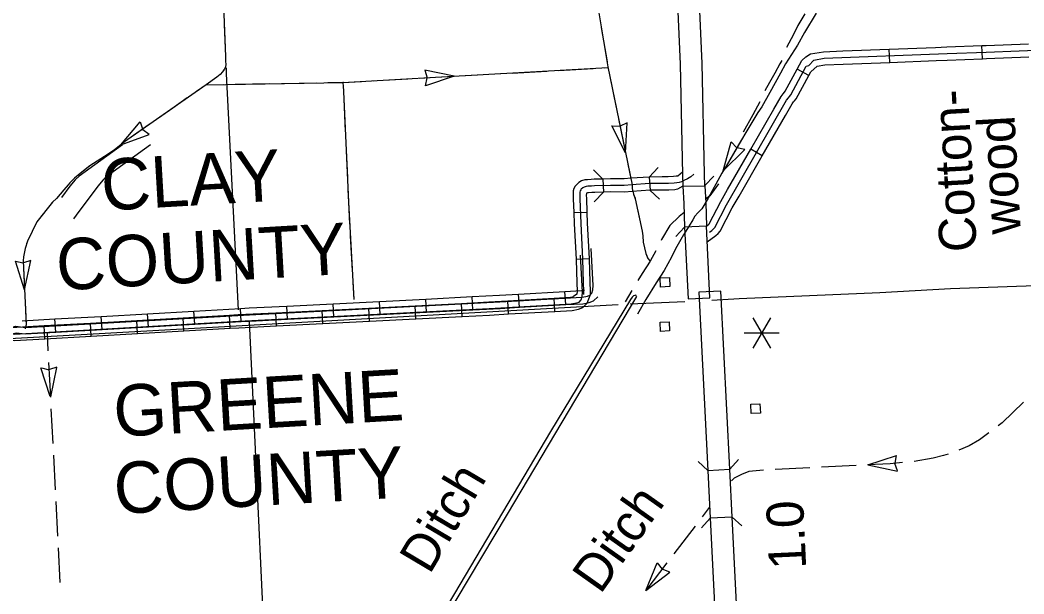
# Model space of a CAD drawing. Extents: x -0.3 to 2.65, y 0 to 1.9.
# Drawn here: x 0.7254 to 0.8619, y 0.3171 to 0.3953 of the extents above; entities that cross this region are included whole.
import ezdxf

# ---------------------------------------------------------------- set-up
doc = ezdxf.new("R2010")
doc.units = 0
for name, color, linetype in [('Level 10', 7, 'Continuous'), ('Level 12', 7, 'Continuous'), ('Level 13', 7, 'Continuous'), ('Level 14', 7, 'Continuous'), ('Level 15', 7, 'Continuous'), ('Level 16', 7, 'Continuous'), ('Level 19', 7, 'Continuous'), ('Level 20', 7, 'Continuous'), ('Level 21', 7, 'Continuous'), ('Level 23', 7, 'Continuous'), ('Level 29', 7, 'Continuous'), ('Level 30', 7, 'Continuous')]:
    doc.layers.add(name, color=color, linetype=linetype)

msp = doc.modelspace()

# ---------------------------------------------------------------- linework, layer by layer
at = {"layer": 'Level 12'}
for p, q in [((0.78041, 0.38846), (0.78075, 0.38742)), ((0.78443, 0.38762), (0.78041, 0.38846)), ((0.78443, 0.38762), (0.78053, 0.38634)), ((0.78053, 0.38634), (0.78075, 0.38741)), ((0.73907, 0.37828), (0.7417, 0.38143)), ((0.7417, 0.38143), (0.74204, 0.38035)), ((0.80797, 0.3813), (0.80699, 0.38081)), ((0.80772, 0.3772), (0.80797, 0.3813)), ((0.74292, 0.37969), (0.74204, 0.38035)), ((0.80772, 0.3772), (0.80589, 0.38088)), ((0.80589, 0.38088), (0.80698, 0.38081)), ((0.73907, 0.37828), (0.74292, 0.37969)), ((0.82103, 0.37475), (0.82213, 0.37871)), ((0.82213, 0.37871), (0.8229, 0.37789)), ((0.82103, 0.37475), (0.82396, 0.37763)), ((0.82396, 0.37763), (0.8229, 0.37789)), ((0.72684, 0.36254), (0.7258, 0.36221)), ((0.72597, 0.35853), (0.72684, 0.36254)), ((0.72945, 0.34402), (0.72819, 0.34793)), ((0.72826, 0.34791), (0.72932, 0.34766)), ((0.73038, 0.34801), (0.72934, 0.34769)), ((0.72952, 0.34396), (0.73038, 0.34797)), ((0.84071, 0.3347), (0.84462, 0.33596)), ((0.84071, 0.3347), (0.84473, 0.33384)), ((0.84458, 0.33599), (0.84439, 0.33491)), ((0.84476, 0.33387), (0.84439, 0.3349)), ((0.8105, 0.31757), (0.81206, 0.32137)), ((0.81206, 0.32137), (0.81273, 0.3205)), ((0.8105, 0.31757), (0.81375, 0.32008)), ((0.81375, 0.32008), (0.81274, 0.32049))]:
    msp.add_line(p, q, dxfattribs=at)
for points in [[(0.79106, 0.46314), (0.79518, 0.44993), (0.79538, 0.44924), (0.79554, 0.44865), (0.79566, 0.44801), (0.79581, 0.4473), (0.80033, 0.41993), (0.80169, 0.41097), (0.80222, 0.40776), (0.80533, 0.3889), (0.80862, 0.37283), (0.80865, 0.37236), (0.80883, 0.37157), (0.80906, 0.37094), (0.80998, 0.36655), (0.81009, 0.36589), (0.81015, 0.36502), (0.81051, 0.36349), (0.81075, 0.3628), (0.81108, 0.36244)], [(0.75278, 0.40422), (0.75329, 0.39033), (0.75329, 0.38968), (0.75333, 0.38925), (0.75331, 0.3889), (0.75318, 0.38857), (0.75292, 0.38824), (0.7526, 0.38788), (0.75215, 0.38752), (0.75067, 0.38648), (0.73956, 0.37868), (0.73818, 0.37755), (0.73684, 0.37672), (0.73487, 0.37543), (0.73352, 0.37437), (0.73276, 0.37373), (0.73214, 0.3731), (0.7319, 0.37284), (0.73131, 0.37218), (0.73029, 0.37098), (0.72977, 0.37046), (0.72762, 0.36781)], [(0.83366, 0.39622), (0.83211, 0.39357), (0.83114, 0.39187), (0.82952, 0.3893), (0.82884, 0.38803), (0.82808, 0.38674), (0.82737, 0.38542), (0.82629, 0.38348), (0.82575, 0.3827), (0.8241, 0.37998), (0.82351, 0.37899), (0.82143, 0.37537), (0.82082, 0.37443), (0.81896, 0.37103), (0.81811, 0.36959), (0.81757, 0.36902), (0.81718, 0.36858), (0.81689, 0.36808), (0.81639, 0.36724), (0.81564, 0.36604), (0.81453, 0.36411), (0.81398, 0.36301), (0.81298, 0.36117), (0.8119, 0.35949), (0.81051, 0.35721), (0.80937, 0.35523)], [(0.83212, 0.39612), (0.83119, 0.39453), (0.8306, 0.39333), (0.82965, 0.39156)], [(0.75313, 0.39474), (0.75329, 0.39033), (0.75329, 0.39)], [(0.80444, 0.39426), (0.80522, 0.38959)], [(0.82902, 0.38977), (0.82875, 0.38933), (0.82807, 0.38806), (0.82731, 0.38677), (0.8267, 0.38564)], [(0.7531, 0.38848), (0.75292, 0.38824), (0.7526, 0.38788), (0.75215, 0.38752), (0.75067, 0.38648), (0.74938, 0.38557)], [(0.75067, 0.38648), (0.76937, 0.38679), (0.76929, 0.38677), (0.77393, 0.38704), (0.78187, 0.38748), (0.80531, 0.38881)], [(0.78837, 0.38785), (0.79074, 0.38798)], [(0.79231, 0.38807), (0.79705, 0.38834)], [(0.79862, 0.38843), (0.80335, 0.3887)], [(0.80493, 0.38879), (0.80531, 0.38881)], [(0.80551, 0.38804), (0.80646, 0.38339)], [(0.75462, 0.38655), (0.75936, 0.38663)], [(0.76094, 0.38665), (0.76568, 0.38673)], [(0.76725, 0.38676), (0.76937, 0.38679), (0.76929, 0.38677), (0.77181, 0.38692)], [(0.7708, 0.35723), (0.77007, 0.37048), (0.76945, 0.38455), (0.76938, 0.38643), (0.76929, 0.38677)], [(0.76938, 0.38642), (0.76938, 0.38643), (0.76929, 0.38677)], [(0.77339, 0.38701), (0.77393, 0.38704), (0.77812, 0.38727)], [(0.7797, 0.38736), (0.78187, 0.38748), (0.78443, 0.38762)], [(0.78601, 0.38771), (0.78837, 0.38785)], [(0.75067, 0.38648), (0.75304, 0.38652)], [(0.74809, 0.38467), (0.74615, 0.3833)], [(0.76965, 0.3801), (0.76945, 0.38455), (0.76944, 0.38484)], [(0.82602, 0.38415), (0.82507, 0.38237), (0.82376, 0.37999)], [(0.74615, 0.3833), (0.74421, 0.38194)], [(0.80677, 0.38185), (0.80772, 0.3772)], [(0.74292, 0.38104), (0.73956, 0.37868), (0.73907, 0.37828)], [(0.76993, 0.37379), (0.76972, 0.37853)], [(0.82343, 0.37884), (0.82143, 0.37537), (0.82103, 0.37475)], [(0.73781, 0.37732), (0.73684, 0.37672), (0.73487, 0.37543), (0.73389, 0.37466)], [(0.80804, 0.37566), (0.80844, 0.37372)], [(0.73268, 0.37365), (0.73214, 0.3731), (0.7319, 0.37284), (0.73131, 0.37218), (0.73029, 0.37098), (0.72977, 0.37046), (0.72951, 0.37014)], [(0.82038, 0.37299), (0.8192, 0.37133), (0.81863, 0.3709)], [(0.77024, 0.36748), (0.77007, 0.37048), (0.77, 0.37222)], [(0.80875, 0.37194), (0.80883, 0.37157), (0.80903, 0.37103)], [(0.72851, 0.36891), (0.72762, 0.36781), (0.72762, 0.36781), (0.72636, 0.36515), (0.72625, 0.36479)], [(0.80937, 0.36949), (0.80998, 0.36655), (0.81009, 0.36589), (0.81015, 0.36502), (0.8102, 0.36483)], [(0.81571, 0.36907), (0.81503, 0.36854), (0.81375, 0.36732), (0.81375, 0.36732)], [(0.72762, 0.36781), (0.72636, 0.36515), (0.72606, 0.36415), (0.7258, 0.36305), (0.72578, 0.36249), (0.72619, 0.3539), (0.72615, 0.35365), (0.72604, 0.35323)], [(0.81375, 0.36732), (0.81264, 0.36539), (0.81257, 0.36526)], [(0.77058, 0.36117), (0.77033, 0.36591)], [(0.81185, 0.36386), (0.81108, 0.36244), (0.81, 0.36076), (0.80941, 0.3598)], [(0.72585, 0.36326), (0.7258, 0.36305), (0.72578, 0.36249), (0.72597, 0.35853)], [(0.81058, 0.3633), (0.81075, 0.3628), (0.81108, 0.36244)], [(0.7708, 0.35723), (0.77067, 0.3596)], [(0.80859, 0.35845), (0.80769, 0.35691)], [(0.72604, 0.35695), (0.72615, 0.35459)], [(0.72615, 0.35459), (0.72619, 0.35371)], [(0.72615, 0.35459), (0.72619, 0.35371)], [(0.72902, 0.3527), (0.72915, 0.35022)], [(0.72923, 0.34864), (0.72935, 0.34628)], [(0.72935, 0.34628), (0.72948, 0.34391)], [(0.86191, 0.34326), (0.859, 0.34043), (0.85846, 0.34003)], [(0.72956, 0.34233), (0.7298, 0.3376)], [(0.85719, 0.33908), (0.8559, 0.33813), (0.8545, 0.33731), (0.85311, 0.33672)], [(0.72989, 0.33602), (0.73013, 0.33129)], [(0.85163, 0.33618), (0.85098, 0.33596), (0.84958, 0.3356), (0.84701, 0.33516)], [(0.84544, 0.335), (0.84376, 0.33485), (0.84071, 0.3347)], [(0.82651, 0.33397), (0.82599, 0.33395), (0.82452, 0.33381), (0.8235, 0.33341), (0.8225, 0.33287), (0.82214, 0.33252)], [(0.83282, 0.33429), (0.82809, 0.33405)], [(0.83913, 0.33462), (0.8344, 0.33437)], [(0.73021, 0.32971), (0.73046, 0.32498)], [(0.81914, 0.32891), (0.81816, 0.32762)], [(0.8172, 0.32636), (0.81433, 0.32259)], [(0.73054, 0.3234), (0.73078, 0.31867)], [(0.81337, 0.32134), (0.8105, 0.31757)]]:
    msp.add_lwpolyline(points, dxfattribs=at)
at = {"layer": 'Level 13'}
for p, q in [((0.84368, 0.38952), (0.84361, 0.39132)), ((0.85631, 0.39001), (0.85624, 0.39181)), ((0.83267, 0.38774), (0.83109, 0.38859)), ((0.82634, 0.37679), (0.82478, 0.37768))]:
    msp.add_line(p, q, dxfattribs=at)
for points in [[(0.85624, 0.39181), (0.8568, 0.39183), (0.86256, 0.39204)], [(0.83109, 0.38859), (0.83173, 0.38977), (0.83225, 0.39029), (0.83291, 0.39068), (0.83467, 0.39096), (0.8373, 0.39107)], [(0.83476, 0.39007), (0.85148, 0.39073), (0.85683, 0.39093), (0.87026, 0.39143), (0.87563, 0.39166), (0.87807, 0.39179)], [(0.8373, 0.39107), (0.84361, 0.39132)], [(0.84361, 0.39132), (0.84993, 0.39156)], [(0.84993, 0.39156), (0.85145, 0.39162), (0.85624, 0.39181)], [(0.81916, 0.36641), (0.81946, 0.36662), (0.8197, 0.36684), (0.81987, 0.36704), (0.82148, 0.37013), (0.82966, 0.38437), (0.82989, 0.38469), (0.83004, 0.38486), (0.83023, 0.38508), (0.83233, 0.389), (0.83266, 0.38908), (0.83336, 0.38984), (0.83476, 0.39007)], [(0.83737, 0.38927), (0.84368, 0.38952)], [(0.84368, 0.38952), (0.85, 0.38977)], [(0.85, 0.38977), (0.85152, 0.38983), (0.85631, 0.39001)], [(0.85631, 0.39001), (0.85687, 0.39003), (0.86262, 0.39025)], [(0.82793, 0.38316), (0.8289, 0.38486), (0.82918, 0.38524), (0.82935, 0.38544), (0.82948, 0.38559), (0.83109, 0.38859)], [(0.83267, 0.38774), (0.83294, 0.38823), (0.83381, 0.38901), (0.83485, 0.38917), (0.83737, 0.38927)], [(0.82949, 0.38227), (0.83041, 0.38388), (0.83059, 0.38413), (0.83072, 0.38428), (0.83097, 0.38457), (0.83267, 0.38774)], [(0.82478, 0.37768), (0.82793, 0.38316)], [(0.82634, 0.37679), (0.82949, 0.38227)], [(0.82163, 0.37221), (0.82478, 0.37768)], [(0.82319, 0.37131), (0.82634, 0.37679)], [(0.81877, 0.3672), (0.81905, 0.36746), (0.81912, 0.36754), (0.82069, 0.37056), (0.82163, 0.37221)], [(0.81884, 0.36509), (0.82003, 0.36592), (0.82035, 0.36621), (0.82062, 0.36653), (0.82226, 0.3697), (0.82319, 0.37131)]]:
    msp.add_lwpolyline(points, dxfattribs=at)
at = {"layer": 'Level 14'}
for points in [[(0.7393, 0.37828), (0.73338, 0.374), (0.73285, 0.37351), (0.73213, 0.37266), (0.73098, 0.37112)], [(0.74312, 0.37828), (0.7372, 0.374), (0.73667, 0.37351), (0.73594, 0.37266), (0.73299, 0.36871), (0.73262, 0.36823)], [(0.80924, 0.35762), (0.80916, 0.35782), (0.8088, 0.35773), (0.80862, 0.35753), (0.8084, 0.35723), (0.79755, 0.33926), (0.77127, 0.2949)], [(0.80924, 0.35762), (0.79164, 0.32797), (0.77248, 0.29587), (0.77149, 0.29411)]]:
    msp.add_lwpolyline(points, dxfattribs=at)
at = {"layer": 'Level 15'}
for p, q in [((0.80467, 0.37363), (0.80472, 0.37184)), ((0.81094, 0.37389), (0.81107, 0.3721)), ((0.80069, 0.36905), (0.80248, 0.36912)), ((0.72597, 0.35853), (0.72472, 0.36244)), ((0.72472, 0.36244), (0.72579, 0.36221)), ((0.801, 0.36273), (0.8028, 0.36282)), ((0.79329, 0.35616), (0.79319, 0.35795)), ((0.7996, 0.35652), (0.7995, 0.35831)), ((0.76805, 0.35486), (0.76795, 0.35665)), ((0.77436, 0.35518), (0.77426, 0.35697)), ((0.78067, 0.3555), (0.78057, 0.35729)), ((0.7855, 0.35491), (0.78541, 0.3567)), ((0.78698, 0.35582), (0.78688, 0.35761)), ((0.79181, 0.35525), (0.79171, 0.35704)), ((0.79812, 0.35561), (0.79802, 0.3574)), ((0.74281, 0.35349), (0.74271, 0.35528)), ((0.74912, 0.35385), (0.74902, 0.35564)), ((0.75543, 0.35421), (0.75533, 0.356)), ((0.76026, 0.35363), (0.76017, 0.35542)), ((0.76174, 0.35454), (0.76164, 0.35633)), ((0.76657, 0.35395), (0.76648, 0.35574)), ((0.77288, 0.35427), (0.77279, 0.35606)), ((0.77919, 0.35459), (0.7791, 0.35638)), ((0.7302, 0.35277), (0.7301, 0.35457)), ((0.73503, 0.35222), (0.73493, 0.35402)), ((0.73651, 0.35313), (0.73641, 0.35492)), ((0.74134, 0.35258), (0.74124, 0.35437)), ((0.74765, 0.35294), (0.74754, 0.35473)), ((0.75395, 0.3533), (0.75385, 0.35509)), ((0.72872, 0.35187), (0.72862, 0.35366))]:
    msp.add_line(p, q, dxfattribs=at)
for points in [[(0.81701, 0.37427), (0.81663, 0.37394), (0.81615, 0.37365), (0.81568, 0.37341), (0.81537, 0.37327), (0.81505, 0.37316), (0.81472, 0.37312), (0.81434, 0.37308), (0.81359, 0.37301), (0.81273, 0.37302), (0.81101, 0.373), (0.80858, 0.37283), (0.80757, 0.37276), (0.80571, 0.37276), (0.8035, 0.3727), (0.80311, 0.37267), (0.80263, 0.37264), (0.80239, 0.37262), (0.80211, 0.37254), (0.80191, 0.37243), (0.80172, 0.37226), (0.80164, 0.37217), (0.80156, 0.37201), (0.80151, 0.37186), (0.8015, 0.37144), (0.80151, 0.37094), (0.80164, 0.36758), (0.8019, 0.36271), (0.80199, 0.35953), (0.80204, 0.35835), (0.80203, 0.35792)], [(0.8155, 0.37458), (0.81485, 0.37404), (0.81461, 0.37401), (0.81426, 0.37397), (0.81356, 0.37391), (0.81273, 0.37392), (0.81097, 0.37389), (0.81094, 0.37389)], [(0.80467, 0.37363), (0.80346, 0.3736), (0.80305, 0.37357), (0.80256, 0.37354), (0.80222, 0.37351), (0.80175, 0.37337), (0.80139, 0.37316), (0.80109, 0.3729), (0.80088, 0.37268), (0.80072, 0.37235), (0.80062, 0.37201), (0.8006, 0.37144), (0.80062, 0.37091), (0.80069, 0.36905)], [(0.81094, 0.37389), (0.80852, 0.37373), (0.80754, 0.37366), (0.8057, 0.37366), (0.80467, 0.37363)], [(0.80472, 0.37184), (0.80354, 0.3718), (0.80317, 0.37178), (0.8027, 0.37175), (0.80255, 0.37173), (0.80246, 0.37171), (0.80242, 0.37169), (0.80241, 0.37167), (0.8024, 0.37144), (0.80241, 0.37097), (0.80248, 0.36912)], [(0.81107, 0.3721), (0.80864, 0.37194), (0.8076, 0.37186), (0.80572, 0.37187), (0.80472, 0.37184)], [(0.81555, 0.37264), (0.81483, 0.37223), (0.81443, 0.37218), (0.81362, 0.37212), (0.81274, 0.37213), (0.81105, 0.3721), (0.81107, 0.3721)], [(0.80069, 0.36905), (0.80075, 0.36754), (0.801, 0.36273)], [(0.80248, 0.36912), (0.80254, 0.36762), (0.8028, 0.36282)], [(0.54078, 0.3466), (0.54109, 0.34658), (0.57017, 0.34792), (0.61968, 0.34958), (0.64273, 0.35053), (0.67386, 0.35128), (0.68769, 0.35175), (0.72378, 0.35333), (0.72478, 0.35357), (0.72608, 0.35342), (0.75657, 0.35515), (0.79065, 0.35689), (0.80184, 0.35753), (0.80255, 0.35766), (0.80289, 0.35779), (0.80317, 0.35807), (0.80331, 0.35853), (0.80334, 0.35912), (0.80308, 0.36417)], [(0.5393, 0.34569), (0.53962, 0.34567), (0.5687, 0.34702), (0.6182, 0.34868), (0.64125, 0.34962), (0.67238, 0.35037), (0.68621, 0.35084), (0.7223, 0.35242), (0.72331, 0.35266), (0.72461, 0.35251), (0.75509, 0.35425), (0.78917, 0.35598), (0.80036, 0.35662), (0.80108, 0.35675), (0.80142, 0.35688), (0.80169, 0.35716), (0.80183, 0.35762), (0.80186, 0.35821), (0.8016, 0.36326)], [(0.801, 0.36273), (0.80101, 0.36268), (0.80109, 0.3595), (0.80115, 0.35835), (0.80113, 0.35795), (0.80068, 0.35761)], [(0.8028, 0.36282), (0.8028, 0.36275), (0.80289, 0.35957), (0.80294, 0.35836), (0.80293, 0.35788), (0.80247, 0.35669)], [(0.78688, 0.35761), (0.7906, 0.3578), (0.79319, 0.35795)], [(0.79319, 0.35795), (0.7995, 0.35831)], [(0.7995, 0.35831), (0.80173, 0.35844), (0.80216, 0.35851)], [(0.76164, 0.35633), (0.76795, 0.35665)], [(0.76795, 0.35665), (0.77426, 0.35697)], [(0.77426, 0.35697), (0.78057, 0.35729)], [(0.7791, 0.35638), (0.78541, 0.3567)], [(0.78057, 0.35729), (0.78688, 0.35761)], [(0.78541, 0.3567), (0.78912, 0.35689), (0.79171, 0.35704)], [(0.79171, 0.35704), (0.79802, 0.3574)], [(0.79329, 0.35616), (0.7996, 0.35652)], [(0.79802, 0.3574), (0.80026, 0.35753), (0.80068, 0.35761)], [(0.79812, 0.35561), (0.80047, 0.35574), (0.80132, 0.3559), (0.80191, 0.35613), (0.80247, 0.35669)], [(0.7996, 0.35652), (0.80194, 0.35665), (0.8028, 0.3568), (0.80339, 0.35704), (0.80395, 0.3576)], [(0.73641, 0.35492), (0.74271, 0.35528)], [(0.74271, 0.35528), (0.74902, 0.35564)], [(0.74902, 0.35564), (0.75533, 0.356)], [(0.75385, 0.35509), (0.75504, 0.35516), (0.76017, 0.35542)], [(0.75533, 0.356), (0.75652, 0.35607), (0.76164, 0.35633)], [(0.76017, 0.35542), (0.76648, 0.35574)], [(0.76648, 0.35574), (0.77279, 0.35606)], [(0.76805, 0.35486), (0.77436, 0.35518)], [(0.77279, 0.35606), (0.7791, 0.35638)], [(0.77436, 0.35518), (0.78067, 0.3555)], [(0.78067, 0.3555), (0.78698, 0.35582)], [(0.7855, 0.35491), (0.78922, 0.3551), (0.79181, 0.35525)], [(0.78698, 0.35582), (0.7907, 0.35601), (0.79329, 0.35616)], [(0.79181, 0.35525), (0.79812, 0.35561)], [(0.72564, 0.35431), (0.7301, 0.35457)], [(0.72862, 0.35366), (0.73493, 0.35402)], [(0.7301, 0.35457), (0.73641, 0.35492)], [(0.73493, 0.35402), (0.74124, 0.35437)], [(0.74124, 0.35437), (0.74754, 0.35473)], [(0.74281, 0.35349), (0.74912, 0.35385)], [(0.74754, 0.35473), (0.75385, 0.35509)], [(0.74912, 0.35385), (0.75543, 0.35421)], [(0.75543, 0.35421), (0.75662, 0.35427), (0.76174, 0.35454)], [(0.76026, 0.35363), (0.76657, 0.35395)], [(0.76174, 0.35454), (0.76805, 0.35486)], [(0.76657, 0.35395), (0.77288, 0.35427)], [(0.77288, 0.35427), (0.77919, 0.35459)], [(0.77919, 0.35459), (0.7855, 0.35491)], [(0.72407, 0.3525), (0.72484, 0.35268), (0.72606, 0.35254), (0.7302, 0.35277)], [(0.72417, 0.3534), (0.72862, 0.35366)], [(0.7302, 0.35277), (0.73651, 0.35313)], [(0.73503, 0.35222), (0.74134, 0.35258)], [(0.73651, 0.35313), (0.74281, 0.35349)], [(0.74134, 0.35258), (0.74765, 0.35294)], [(0.74765, 0.35294), (0.75395, 0.3533)], [(0.75395, 0.3533), (0.75514, 0.35337), (0.76026, 0.35363)], [(0.7226, 0.35159), (0.72336, 0.35177), (0.72458, 0.35163), (0.72872, 0.35187)], [(0.72872, 0.35187), (0.73503, 0.35222)]]:
    msp.add_lwpolyline(points, dxfattribs=at)
at = {"layer": 'Level 16'}
for p, q in [((0.82746, 0.35474), (0.82507, 0.3506)), ((0.82507, 0.35474), (0.82746, 0.3506)), ((0.82387, 0.35267), (0.82866, 0.35267))]:
    msp.add_line(p, q, dxfattribs=at)
at = {"layer": 'Level 19'}
for points in [[(0.81251, 0.35892), (0.81245, 0.36017), (0.8137, 0.36022), (0.81376, 0.35898)], [(0.81248, 0.35288), (0.81243, 0.35413), (0.81368, 0.35418), (0.81373, 0.35294)], [(0.82484, 0.3417), (0.82478, 0.34295), (0.82603, 0.343), (0.82608, 0.34176)]]:
    msp.add_lwpolyline(points, close=True, dxfattribs=at)
at = {"layer": 'Level 20'}
for points in [[(0.75339, 0.38878), (0.75342, 0.38794), (0.75505, 0.35581)], [(0.75655, 0.35426), (0.75939, 0.29315)]]:
    msp.add_lwpolyline(points, dxfattribs=at)
at = {"layer": 'Level 21'}
for points in [[(0.81443, 0.4681), (0.81144, 0.46796), (0.81373, 0.42057), (0.81434, 0.40771), (0.81519, 0.38928), (0.81551, 0.37423), (0.81555, 0.37264), (0.81855, 0.37272)], [(0.81855, 0.37272), (0.8185, 0.3743), (0.81818, 0.38938), (0.81733, 0.40785), (0.81672, 0.42071), (0.81443, 0.4681)], [(0.81555, 0.37264), (0.81566, 0.37028), (0.81578, 0.36709)], [(0.81855, 0.37272), (0.81865, 0.37041), (0.81877, 0.3672)], [(0.81923, 0.35746), (0.81877, 0.3672), (0.81578, 0.36709)], [(0.81578, 0.36709), (0.81624, 0.35731), (0.81923, 0.35746)], [(0.82071, 0.35836), (0.81772, 0.35822)], [(0.81772, 0.35822), (0.81893, 0.33395)], [(0.82192, 0.3341), (0.82071, 0.35836)], [(0.81893, 0.33395), (0.82192, 0.3341)], [(0.81893, 0.33395), (0.81926, 0.32744)], [(0.82225, 0.32759), (0.82192, 0.3341)], [(0.82225, 0.32759), (0.81926, 0.32744)], [(0.81926, 0.32744), (0.82079, 0.2967)], [(0.82378, 0.29682), (0.82225, 0.32759)]]:
    msp.add_lwpolyline(points, dxfattribs=at)
at = {"layer": 'Level 23'}
for points in [[(0.81948, 0.35714), (0.82319, 0.35735), (0.84236, 0.35817), (0.85194, 0.35871), (0.87892, 0.35967)], [(0.70034, 0.35058), (0.80674, 0.35653)], [(0.80836, 0.35661), (0.81582, 0.35695)]]:
    msp.add_lwpolyline(points, dxfattribs=at)
at = {"layer": 'Level 29'}
for points in [[(0.80337, 0.37486), (0.80467, 0.37363)], [(0.81097, 0.37389), (0.81218, 0.37522)], [(0.80472, 0.37184), (0.80349, 0.37053)], [(0.81237, 0.37089), (0.81104, 0.3721)]]:
    msp.add_lwpolyline(points, dxfattribs=at)
at = {"layer": 'Level 30'}
for points in [[(0.81977, 0.37404), (0.81854, 0.37273)], [(0.81556, 0.37262), (0.81556, 0.37262)], [(0.81456, 0.36578), (0.81578, 0.36709)], [(0.81877, 0.3672), (0.81877, 0.3672)], [(0.81893, 0.33395), (0.8176, 0.33516)], [(0.82313, 0.33543), (0.82192, 0.3341)], [(0.81806, 0.32611), (0.81926, 0.32744)], [(0.82225, 0.32759), (0.82358, 0.32638)]]:
    msp.add_lwpolyline(points, dxfattribs=at)

# ---------------------------------------------------------------- texts
at = {"layer": 'Level 10'}
for s, p in [('CLAY', (0.73658, 0.3693)), (' COUNTY', (0.72786, 0.35828)), ('GREENE ', (0.73826, 0.3385)), ('COUNTY', (0.7383, 0.32798))]:
    msp.add_text(s, height=0.007, rotation=3.3249, dxfattribs=at).set_placement(p)
at = {"layer": 'Level 12'}
for s, height, rotation, p in [('Cotton-', 0.00505, 93.1678, (0.85555, 0.36382)), ('wood', 0.00505, 93.1678, (0.86154, 0.36627)), ('Ditch', 0.005055, 54.6888, (0.80431, 0.31696))]:
    msp.add_text(s, height=height, rotation=rotation, dxfattribs=at).set_placement(p)
at = {"layer": 'Level 14'}
msp.add_text('Ditch', height=0.005055, rotation=59.2776, dxfattribs=at).set_placement((0.78108, 0.31966))
at = {"layer": 'Level 16'}
msp.add_text('1.0', height=0.005055, rotation=92.6785, dxfattribs=at).set_placement((0.83233, 0.32058))

doc.saveas('drawing.dxf')
